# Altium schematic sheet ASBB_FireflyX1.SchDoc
size A4
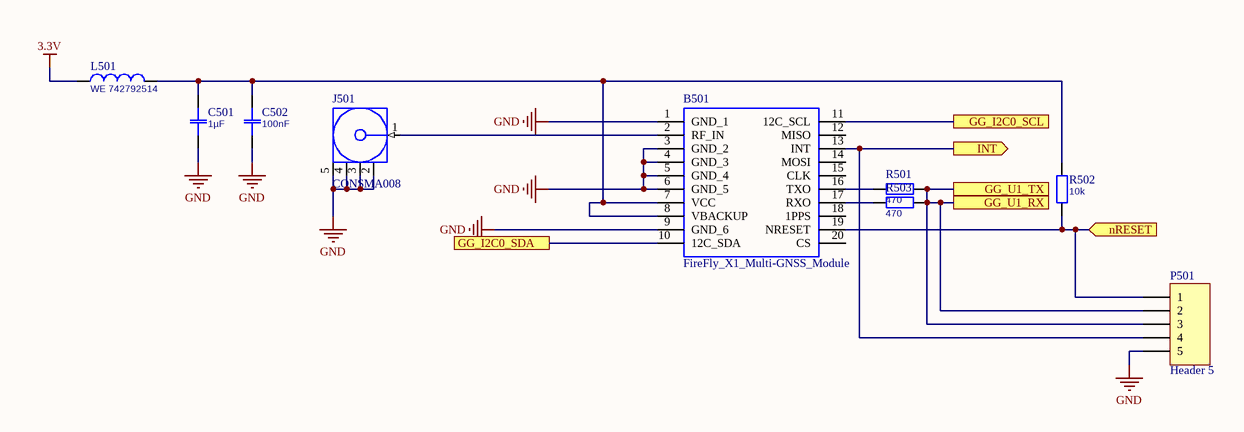
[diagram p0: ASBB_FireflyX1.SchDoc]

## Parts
B501  FireFly_X1_Multi-GNSS_Module  [X-1]
C501  1µF  [0603]
C502  100nF  [0603]
J501  CONSMA008  [CON-SMA-L]
L501  WE 742792514  [1812]
P501  Header 5  [HDR1X5]
R501  470  [0603]
R502  10k  [0603]
R503  470  [0603]

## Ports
GG_I2C0_SCL, GG_I2C0_SDA, GG_U1_RX, GG_U1_TX, INT (out), nRESET (in)

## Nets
3.3V: L501.1
GND: B501.1(GND_1) B501.3(GND_2) B501.4(GND_3) B501.5(GND_4) B501.6(GND_5) B501.9(GND_6) C501.1 C502.1 J501.2(GND) J501.3(GND) J501.4(GND) J501.5(GND) P501.5
GG_I2C0_SCL: B501.11(12C_SCL) ; port GG_I2C0_SCL
GG_I2C0_SDA: B501.10(12C_SDA) ; port GG_I2C0_SDA
GG_U1_RX: P501.2 P501.3 R501.2 R503.2 ; port GG_U1_TX, port GG_U1_RX
INT: B501.13(INT) P501.4 ; port INT
nRESET: B501.19(NRESET) P501.1 R502.1 ; port nRESET
NetB501_2: B501.2(RF_IN) J501.1(Signal)
NetB501_7: B501.7(VCC) B501.8(VBACKUP) C501.2 C502.2 L501.2 R502.2
NetB501_16: B501.16(TXO) R501.1
NetB501_17: B501.17(RXO) R503.1

Not connected (* = marked no-connect by the designer): B501 12(MISO) 14(MOSI) 15(CLK) 18(1PPS) 20(CS)

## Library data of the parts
B501 = FireFly_X1_Multi-GNSS_Module: Dual system GNSS receiver Module, QFN-20; Manufacturer_Name: GlobalTop Technology Inc.; Manufacturer_Part_Number: FireFly X1 Multi-GNSS Module
C501 C502 = Capacitor
J501 = CONSMA008: SMA Female PCB Mount Connector - Extended
L501 = Inductor
P501 = Header 5: Header, 5-Pin
R501-R503 = Resistor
